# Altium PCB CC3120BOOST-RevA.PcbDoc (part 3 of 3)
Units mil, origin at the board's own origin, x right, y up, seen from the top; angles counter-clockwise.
Board outline 2300 x 1700 mil, 4 copper layers (Top Layer, Mid-Layer 1, Mid-Layer 2, Bottom Layer), stack 90 mil thick; 155 components, 108 nets, 432 pads, 292 vias.
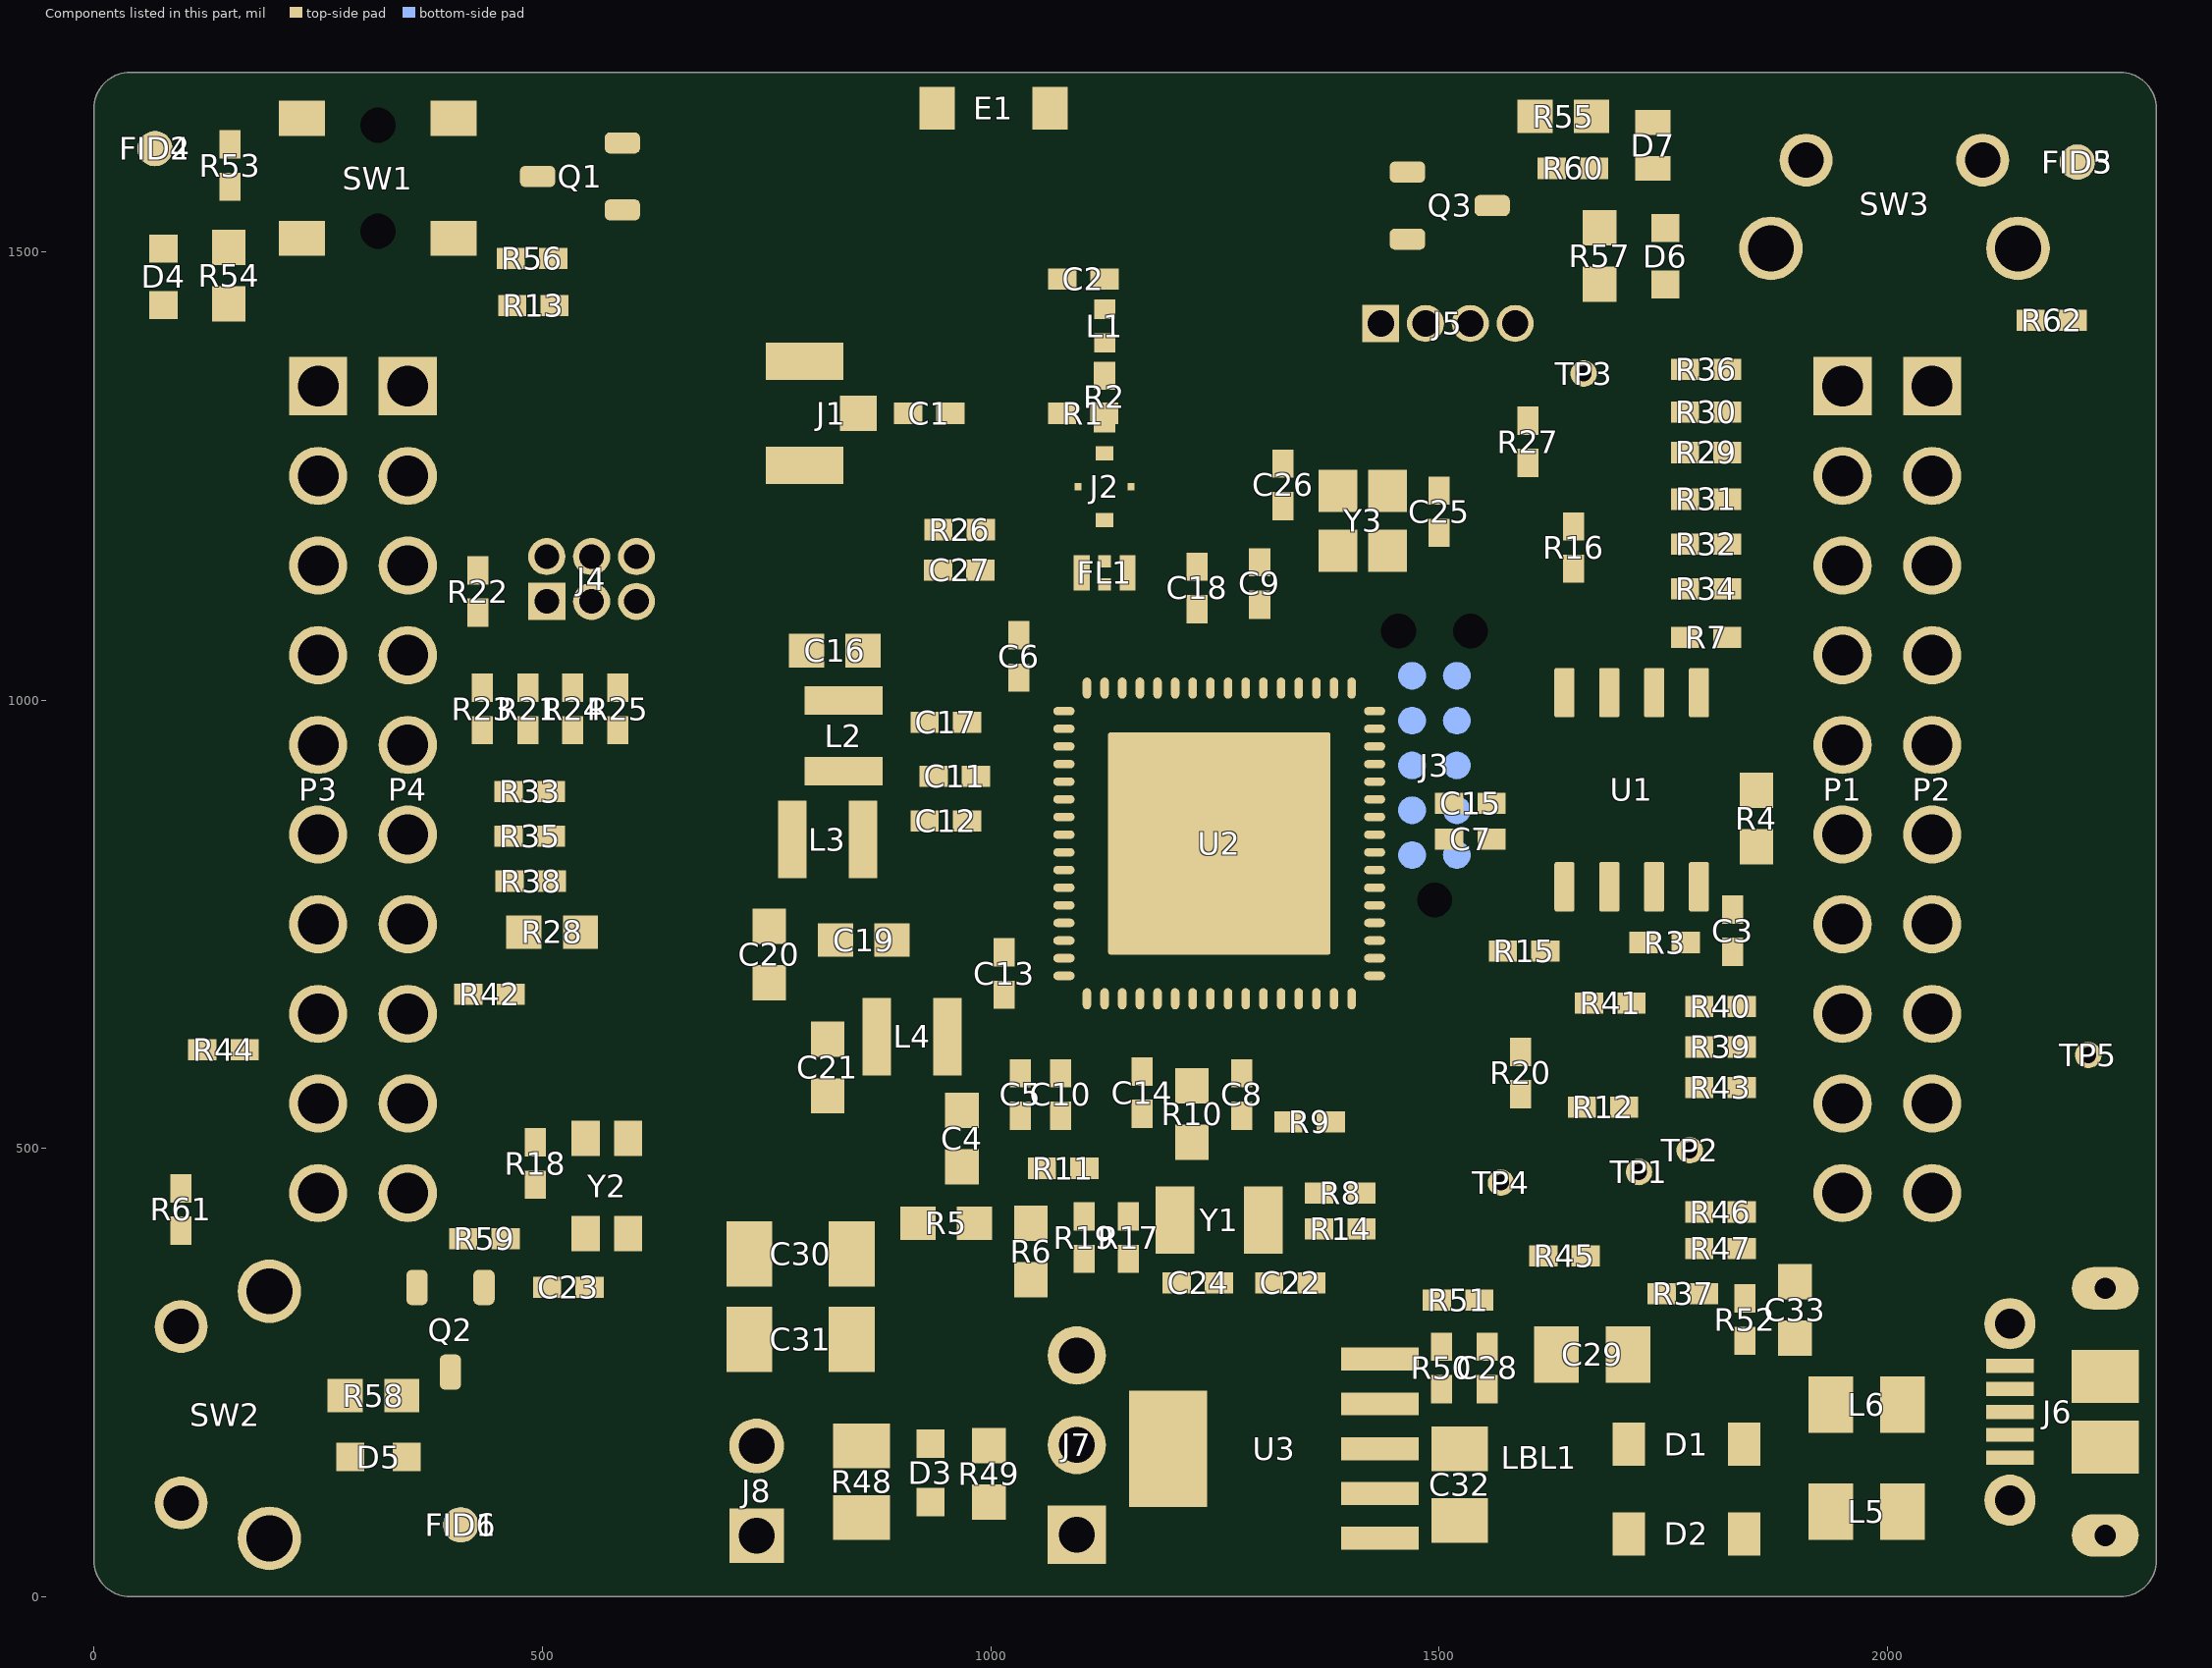
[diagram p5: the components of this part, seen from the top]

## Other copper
Top Layer:
  rectangle net GND: 1107,692 1402.28,987.28
  pour cut-out: 700,1210 716.9,1193.1 727.4,1193.1 724.5,1196 724.5,1220.6 704.3,1220.6 700,1216.3
  pour cut-out: 432.2,925 465.8,925 477.2,936.4 477.2,1000.4 467.5,1010.1 439.7,1010.1 418.1,988.5 418.1,936.4 429.3,925.2 432,925.2
  pour cut-out: 1519.7,259.4 1526.2,252.9 1535.7,252.9 1545.3,262.5 1545.3,291.5 1528.3,308.5 1524,304.2 1519.7,304.2
  pour cut-out: 744.8,460.7 772.9,488.8 909,488.8 915.2,482.6 918.5,482.6 932.5,496.6 932.5,515.6 877.2,570.9 720,570.9 701.4,552.3 701.4,480.5 723.3,458.6 726.4,461.7 745.5,461.7
  pour cut-out: 1005.6,1106.3 1005.6,1061.5 1018,1049.1 1049.1,1049.1 1055.5,1055.5 1055.5,1113.5 1042.2,1126.8 1024.3,1126.8 1004.7,1107.2
  pour cut-out: 753.7,453 661,453 643.33,470.67 643.33,764.33 658,779 658,892 658,1137 715,1194 707,1202 707,1227 713.4,1233.4 963.6,1233.4 967,1230 967,1136 962,1131 948.58,1131 935.4,1117.82 935.4,1038.6 968,1006 1037.8,936.2 1037.8,658.8 932,553 779,553 753.7,527.7
  pour cut-out: 888.04,1292.94 985.87,1292.94 985.87,1294.43 1048.79,1294.43 1048.79,1292.94 1100.19,1292.94 1100.19,1346.56 1048.79,1346.56 1048.79,1343.37 985.87,1343.37 985.87,1346.56 888.04,1346.56
  pour cut-out: 1100.19,1346.56 1100.19,1413.29 1104.7,1417.8 1153.8,1417.8 1153.8,1343.9 1149.5,1339.6 1107.15,1339.6
  region net GND: 1144.77,1225.37 1153.82,1216.31 1172.33,1216.31 1172.33,1259.62 1153.82,1259.62 1144.77,1250.57
  region net GND: 1109.33,1250.57 1100.28,1259.62 1081.77,1259.62 1081.77,1216.31 1100.28,1216.31 1109.33,1225.37
  pour cut-out: 1395.9,424.41 1384.15,436.16 1233.28,436.16 1173.12,376 1173.12,335.58 1175,333.7 1378.98,333.7 1395.9,350.62
  pour cut-out: 1214.24,300.33 1371.69,300.33 1379.68,308.32 1379.68,346.39 1367.46,358.61 1221.29,358.61 1212.36,349.68 1212.36,302.21
  pour cut-out: 1213,1128 1213,1202 1316,1305 1573,1305 1584,1316 1694,1316 1865,1145 1865,559 1767,461 1612,461 1535,538 1535,955 1379,1111 1229.34,1111 1215.22,1125.13
  pour cut-out: 1102,994 1102,694.84 1110.07,686.78 1397.92,686.78 1408.71,697.57 1408.71,984.44 1396.16,997 1105,997
  pour cut-out: 971.91,424.31 1516.43,424.31 1526.97,434.85 1526.97,558.16 1589.2,620.39 1589.2,737.06 1579.56,746.7 1546.58,746.7 1512.08,781.2 1445.73,781.2 1441.18,776.65 1441.18,675.81 1437.01,671.64 1437.01,629.17 1406.68,598.84 920.23,598.84 920.23,476.51 972.6,424.14
  pour cut-out: 1859,259 1857,261 1857,264 1862,269 1912,269 1915,266 1915,260 1914,259
  pour cut-out: 1158,1455 1138,1455 1137,1456 1137,1500 1142,1505 1156,1505 1158,1503
  pour cut-out: 1153.86,1424.2 1153.86,1405.9 1140.1,1405.9 1137,1409 1137,1496 1139,1498 1153,1498 1154,1497 1154,1424
  pour cut-out: 1117,1494.65 940.2,1494.65 940,1494.85 940,1636 961,1636 961,1692 1046,1692 1046,1636 1117,1636
  pour cut-out: 1490.33,1490.33 1439.33,1490.33 1439.33,1537.34 1490.33,1537.34 1490.33,1490.33
  pour cut-out: 287,1313 213,1313 213,1387 287,1387
  pour cut-out: 378.55,889 455.88,811.66 455.88,791 439.56,791 419.56,811 371.35,811 371.01,811.02 370.66,811.06 370.32,811.14 369.99,811.24 369.66,811.38 369.35,811.54 369.06,811.72 368.78,811.94 368.53,812.17 368.29,812.43 368.08,812.71 367.89,813 367.73,813.31 367.6,813.63 367.49,813.97 367.42,814.31 367.37,814.65 367.35,815 367.37,815.35 367.42,815.69 367.49,816.04 367.6,816.37 367.73,816.69 367.89,817 368.08,817.29 368.29,817.57 368.53,817.83 368.78,818.06 369.06,818.28 369.27,818.41 371.95,820.21 374.46,822.24 376.79,824.48 378.91,826.91 380.81,829.52 382.48,832.28 383.9,835.18 385.07,838.19 385.96,841.29 386.58,844.46 386.93,847.67 386.99,850.9 386.77,854.12 386.27,857.31 385.5,860.44 384.45,863.49 383.14,866.45 381.59,869.27 379.79,871.95 377.76,874.46 375.52,876.79 373.09,878.91 370.48,880.81 369.27,881.59 368.98,881.78 368.71,882 368.46,882.24 368.23,882.5 368.02,882.79 367.84,883.08 367.69,883.4 367.56,883.72 367.47,884.06 367.4,884.4 367.36,884.75 367.36,885.1 367.38,885.44 367.43,885.79 367.52,886.13 367.63,886.46 367.77,886.78 367.94,887.08 368.13,887.37 368.35,887.64 368.6,887.9 368.86,888.13 369.14,888.33 369.44,888.51 369.75,888.66 370.08,888.79 370.41,888.89 370.76,888.95 371.1,888.99 371.35,889 378.55,889
  pour cut-out: 1097,1005 1096,1004 1084,1004 1046,1042 1046,1073 1049,1070 1061,1070 1075,1056 1075,1078 1101,1078 1109,1070 1109,1039 1102,1032 1097,1032 1097,1005
  pour cut-out: 1040.99,1031.29 1040.99,1032.71 1054.97,1032.71 1059.83,1027.84 1059.83,1000.78 1058.7,1000.23 1057.67,999.67 1057.36,999.51 1057.04,999.37 1056.71,999.26 1056.37,999.18 1056.03,999.13 1055.68,999.11 1055.33,999.12 1054.98,999.16 1054.64,999.23 1054.31,999.33 1053.98,999.46 1053.67,999.62 1053.37,999.8 1053.09,1000.01 1052.83,1000.24 1052.59,1000.5 1052.38,1000.77 1052.19,1001.06 1052.02,1001.37 1051.88,1001.69 1051.86,1001.76 1051.2,1003.37 1050.4,1004.92 1049.47,1006.4 1048.41,1007.79 1047.24,1009.08 1045.96,1010.26 1044.58,1011.33 1043.11,1012.28 1041.57,1013.09 1039.96,1013.76 1038.3,1014.3 1036.6,1014.68 1034.87,1014.92 1033.12,1015 1031.38,1014.93 1029.65,1014.71 1027.94,1014.34 1027.31,1014.16 1026.97,1014.08 1026.62,1014.02 1026.28,1014 1025.93,1014 1025.58,1014.04 1025.24,1014.1 1024.9,1014.2 1024.58,1014.32 1024.26,1014.48 1023.96,1014.65 1023.68,1014.86 1023.41,1015.09 1023.17,1015.34 1022.95,1015.61 1022.76,1015.9 1022.59,1016.2 1022.44,1016.52 1022.33,1016.85 1022.24,1017.19 1022.19,1017.53 1022.18,1017.6 1021.9,1019.59 1021.44,1021.54 1020.82,1023.45 1020.03,1025.3 1019.92,1025.52 1019.78,1025.84 1019.67,1026.17 1019.58,1026.51 1019.53,1026.86 1019.51,1027.2 1019.51,1027.55 1019.55,1027.9 1019.62,1028.24 1019.72,1028.58 1019.84,1028.9 1020,1029.21 1020.18,1029.51 1020.39,1029.79 1020.62,1030.06 1020.87,1030.3 1021.14,1030.52 1021.43,1030.71 1021.74,1030.88 1022.06,1031.02 1022.39,1031.13 1022.72,1031.21 1023.07,1031.27 1023.42,1031.29 1023.51,1031.29 1040.99,1031.29
  pour cut-out: 1781.88,1087 1699.66,1087 1699.31,1087.02 1698.97,1087.06 1698.63,1087.14 1698.3,1087.24 1697.97,1087.38 1697.66,1087.54 1697.37,1087.72 1697.09,1087.94 1696.84,1088.17 1696.6,1088.43 1696.39,1088.71 1696.2,1089 1696.04,1089.31 1695.9,1089.63 1695.8,1089.96 1695.72,1090.31 1695.68,1090.65 1695.66,1091 1695.68,1091.35 1695.72,1091.69 1695.8,1092.04 1695.9,1092.37 1696.04,1092.69 1696.2,1093 1696.39,1093.29 1696.6,1093.57 1696.84,1093.83 1697.09,1094.06 1697.22,1094.17 1698.55,1095.29 1699.78,1096.53 1700.9,1097.87 1701,1098 1781.88,1098 1781.88,1087
  pour cut-out: 2197.55,96.93 2197.55,302.63 2204.97,310.05 2258.54,310.05 2267.53,301.06 2267.53,102.43 2252.67,87.57 2207.99,87.57 2197.52,98.04
  pour cut-out: 716,1236 687,1236 686,1235 686,1224 700,1210 714,1210 714,1229 716,1231
  pour cut-out: 1005,1172 1012,1179 1035,1179 1055,1159 1055,1070 1024,1070 1004,1090 1005,1091
  pour cut-out: 1158,1494.65 1132.23,1494.65 1126.8,1500.08 1117.03,1500.08 1117,1500.11
  pour cut-out: 1046.01,1636.01 1176.42,1636.01 1176.42,1494.65 1053.68,1494.65 1039.13,1509.2 1046,1516.07 1046,1636
  pour cut-out: 1117.01,1494.66 1117.01,1420.58 1119.04,1418.55 1137.67,1418.55 1141.56,1422.43 1141.56,1493.47 1137.49,1497.54 1119.88,1497.54
  pour cut-out: 808.47,115.38 820.81,127.71 912.74,127.71 912.74,105.13 902.65,95.04 828.01,95.04 808.15,114.9
  pour cut-out: 1580.7,1306.1 1669.6,1306.1 1684.2,1320.7 1684.2,1350.1 1657.4,1376.9 1610.5,1376.9 1574.8,1341.2 1574.8,1309.2 1578,1306 1580.7,1306
  pour cut-out: 744,496.6 764.5,496.6 773.2,505.3 773.2,541.6 752.8,562 752.8,566 695.1,566 688.9,559.8 688.9,507.4 699.6,496.7 745.8,496.7
  pour cut-out: 1101,1413 1101,1499 1104,1502 1113.92,1502 1117,1498.92 1117,1412 1116,1413
  text "L01 TOP LAYER" at 727,-858.49 h60
Mid-Layer 1:
  pour cut-out: 898.42,956.58 906.03,961.67 915,963.45 923.97,961.67 931.58,956.58 936.67,948.97 937.83,943.13 936.8,933.5 922.7,915.7 911.3,917.29 906.03,918.33 898.42,923.42 893.33,931.03 891.55,940 893.33,948.97
  pour cut-out: 880.12,827.82 875.03,835.43 873.25,844.4 875.03,853.37 880.12,860.98 887.73,866.07 893.57,867.23 903.2,866.2 921,852.1 919.41,840.7 918.37,835.43 913.28,827.82 905.67,822.73 896.7,820.95 887.73,822.73
  pour cut-out: 977.22,629.92 972.13,637.53 970.35,646.5 972.13,655.47 977.22,663.08 984.83,668.17 990.67,669.33 1000.3,668.3 1018.1,654.2 1016.51,642.8 1015.47,637.53 1010.38,629.92 1002.77,624.83 993.8,623.05 984.83,624.83
  pour cut-out: 995.95,1026.75 994.4,1034.55 989.98,1041.17 983.36,1045.59 975.56,1047.14 967.75,1045.59 961.14,1041.17 956.72,1034.55 955.16,1026.75 956.72,1018.95 961.14,1012.33 967.75,1007.91 975.56,1006.36 983.36,1007.91 989.98,1012.33 994.4,1018.95 995.95,1026.75
  pour cut-out: 841.91,27.75 873.58,27.75 885.2,39.37 885.2,62.42 878.74,68.88 838.82,68.88 835.54,65.6 835.54,34.02 841.8,27.77
  pour cut-out: 582.55,362.3 582.55,336.06 584.37,334.23 604.45,334.23 605.8,335.58 605.8,359.42 602.93,362.29 582.54,362.29
  pour cut-out: 505.4,1157.5 505.4,1107.5 605.4,1107.5 605.4,1157.5
  pour cut-out: 1530.39,480 1528.84,487.8 1524.42,494.42 1517.8,498.84 1510,500.39 1502.2,498.84 1495.58,494.42 1491.16,487.8 1489.61,480 1491.16,472.2 1495.58,465.58 1502.2,461.16 1510,459.61 1517.8,461.16 1524.42,465.58 1528.84,472.2 1530.39,480
  pour cut-out: 182 vertices and 0 holes, not listed, extent 1556.01,1115.01 1610.99,1194.99
  pour cut-out: 178 vertices and 0 holes, not listed, extent 1510.01,1215.01 1579.99,1284.99
  pour cut-out: 1285.39,1125 1283.84,1132.8 1279.42,1139.42 1272.8,1143.84 1265,1145.39 1257.2,1143.84 1250.58,1139.42 1246.16,1132.8 1244.61,1125 1246.16,1117.2 1250.58,1110.58 1257.2,1106.16 1265,1104.61 1272.8,1106.16 1279.42,1110.58 1283.84,1117.2 1285.39,1125
  pour cut-out: 1250.39,1288 1248.84,1295.8 1244.42,1302.42 1237.8,1306.84 1230,1308.39 1222.2,1306.84 1215.58,1302.42 1211.16,1295.8 1209.61,1288 1211.16,1280.2 1215.58,1273.58 1222.2,1269.16 1230,1267.61 1237.8,1269.16 1244.42,1273.58 1248.84,1280.2 1250.39,1288
  pour cut-out: 640.39,1010 638.84,1017.8 634.42,1024.42 627.8,1028.84 620,1030.39 612.2,1028.84 605.58,1024.42 601.16,1017.8 599.61,1010 601.16,1002.2 605.58,995.58 612.2,991.16 620,989.61 627.8,991.16 634.42,995.58 638.84,1002.2 640.39,1010
  pour cut-out: 625.65,903.44 624.1,911.24 619.68,917.85 613.06,922.28 605.26,923.83 597.46,922.28 590.84,917.85 586.42,911.24 584.87,903.44 586.42,895.63 590.84,889.02 597.46,884.6 605.26,883.04 613.06,884.6 619.68,889.02 624.1,895.63 625.65,903.44
  pour cut-out: 610.39,850 608.84,857.8 604.42,864.42 597.8,868.84 590,870.39 582.2,868.84 575.58,864.42 571.16,857.8 569.61,850 571.16,842.2 575.58,835.58 582.2,831.16 590,829.61 597.8,831.16 604.42,835.58 608.84,842.2 610.39,850
  pour cut-out: 614.99,319.7 613.44,327.5 609.02,334.12 602.4,338.54 594.6,340.09 586.8,338.54 580.18,334.12 575.76,327.5 574.21,319.7 575.76,311.9 580.18,305.28 586.8,300.86 594.6,299.31 602.4,300.86 609.02,305.28 613.44,311.9 614.99,319.7
  text "L02 GND LAYER" at 739,-834 h25
Mid-Layer 2:
  pour cut-out: 628.1,754.7 617.48,765.32 617.48,864.42 633.46,880.4 679.5,880.4 679.5,806.1
  pour cut-out: 526.59,337.8 525.04,345.6 520.62,352.22 514,356.64 506.2,358.19 498.4,356.64 491.78,352.22 487.36,345.6 485.81,337.8 487.36,330 491.78,323.38 498.4,318.96 506.2,317.41 514,318.96 520.62,323.38 525.04,330 526.59,337.8
  pour cut-out: 525.77,314.38 524.22,322.18 519.8,328.8 513.18,333.22 505.38,334.77 497.57,333.22 490.96,328.8 486.54,322.18 484.99,314.38 486.54,306.57 490.96,299.96 497.57,295.54 505.38,293.99 513.18,295.54 519.8,299.96 524.22,306.57 525.77,314.38
  pour cut-out: 644.4,657.4 644.4,520.1 652.6,511.9 711.7,511.9 715.2,515.4 715.2,586.6
  pour cut-out: 810.59,732.2 809.04,740 804.62,746.62 798,751.04 790.2,752.59 782.4,751.04 775.78,746.62 771.36,740 769.81,732.2 771.36,724.4 775.78,717.78 782.4,713.36 790.2,711.81 798,713.36 804.62,717.78 809.04,724.4 810.59,732.2
  pour cut-out: 798.59,560 797.04,567.8 792.62,574.42 786,578.84 778.2,580.39 770.4,578.84 763.78,574.42 759.36,567.8 757.81,560 759.36,552.2 763.78,545.58 770.4,541.16 778.2,539.61 786,541.16 792.62,545.58 797.04,552.2 798.59,560
  pour cut-out: 838.59,520 837.04,527.8 832.62,534.42 826,538.84 818.2,540.39 810.4,538.84 803.78,534.42 799.36,527.8 797.81,520 799.36,512.2 803.78,505.58 810.4,501.16 818.2,499.61 826,501.16 832.62,505.58 837.04,512.2 838.59,520
  pour cut-out: 1014.19,646.5 1012.64,654.3 1008.22,660.92 1001.6,665.34 993.8,666.89 986,665.34 979.38,660.92 974.96,654.3 973.41,646.5 974.96,638.7 979.38,632.08 986,627.66 993.8,626.11 1001.6,627.66 1008.22,632.08 1012.64,638.7 1014.19,646.5
  pour cut-out: 810.59,732.2 809.04,740 804.62,746.62 798,751.04 790.2,752.59 782.4,751.04 775.78,746.62 771.36,740 769.81,732.2 771.36,724.4 775.78,717.78 782.4,713.36 790.2,711.81 798,713.36 804.62,717.78 809.04,724.4 810.59,732.2
  pour cut-out: 1616.29,838.28 1614.74,846.08 1610.32,852.7 1603.7,857.12 1595.9,858.67 1588.1,857.12 1581.48,852.7 1577.06,846.08 1575.51,838.28 1577.06,830.48 1581.48,823.86 1588.1,819.44 1595.9,817.89 1603.7,819.44 1610.32,823.86 1614.74,830.48 1616.29,838.28
  pour cut-out: 1074.39,503.5 1072.84,511.3 1068.42,517.92 1061.8,522.34 1054,523.89 1046.2,522.34 1039.58,517.92 1035.16,511.3 1033.61,503.5 1035.16,495.7 1039.58,489.08 1046.2,484.66 1054,483.11 1061.8,484.66 1068.42,489.08 1072.84,495.7 1074.39,503.5
  pour cut-out: 1046.29,477.7 1044.74,485.5 1040.32,492.12 1033.7,496.54 1025.9,498.09 1018.1,496.54 1011.48,492.12 1007.06,485.5 1005.51,477.7 1007.06,469.9 1011.48,463.28 1018.1,458.86 1025.9,457.31 1033.7,458.86 1040.32,463.28 1044.74,469.9 1046.29,477.7
  pour cut-out: 1053.39,506 1051.84,513.8 1047.42,520.42 1040.8,524.84 1033,526.39 1025.2,524.84 1018.58,520.42 1014.16,513.8 1012.61,506 1014.16,498.2 1018.58,491.58 1025.2,487.16 1033,485.61 1040.8,487.16 1047.42,491.58 1051.84,498.2 1053.39,506
  pour cut-out: 1106.29,1145.3 1104.74,1153.1 1100.32,1159.72 1093.7,1164.14 1085.9,1165.69 1078.1,1164.14 1071.48,1159.72 1067.06,1153.1 1065.51,1145.3 1067.06,1137.5 1071.48,1130.88 1078.1,1126.46 1085.9,1124.91 1093.7,1126.46 1100.32,1130.88 1104.74,1137.5 1106.29,1145.3
  pour cut-out: 1107.39,1166 1105.84,1173.8 1101.42,1180.42 1094.8,1184.84 1087,1186.39 1079.2,1184.84 1072.58,1180.42 1068.16,1173.8 1066.61,1166 1068.16,1158.2 1072.58,1151.58 1079.2,1147.16 1087,1145.61 1094.8,1147.16 1101.42,1151.58 1105.84,1158.2 1107.39,1166
  pour cut-out: 1106.39,1121 1104.84,1128.8 1100.42,1135.42 1093.8,1139.84 1086,1141.39 1078.2,1139.84 1071.58,1135.42 1067.16,1128.8 1065.61,1121 1067.16,1113.2 1071.58,1106.58 1078.2,1102.16 1086,1100.61 1093.8,1102.16 1100.42,1106.58 1104.84,1113.2 1106.39,1121
  pour cut-out: 1106.39,1089.44 1104.84,1097.25 1100.42,1103.86 1093.8,1108.28 1086,1109.84 1078.2,1108.28 1071.58,1103.86 1067.16,1097.25 1065.61,1089.44 1067.16,1081.64 1071.58,1075.03 1078.2,1070.6 1086,1069.05 1093.8,1070.6 1100.42,1075.03 1104.84,1081.64 1106.39,1089.44
  pour cut-out: 1051.99,1105.7 1050.44,1113.5 1046.02,1120.12 1039.4,1124.54 1031.6,1126.09 1023.8,1124.54 1017.18,1120.12 1012.76,1113.5 1011.21,1105.7 1012.76,1097.9 1017.18,1091.28 1023.8,1086.86 1031.6,1085.31 1039.4,1086.86 1046.02,1091.28 1050.44,1097.9 1051.99,1105.7
  pour cut-out: 773.39,781.3 771.84,789.1 767.42,795.72 760.8,800.14 753,801.69 745.2,800.14 738.58,795.72 734.16,789.1 732.61,781.3 734.16,773.5 738.58,766.88 745.2,762.46 753,760.91 760.8,762.46 767.42,766.88 771.84,773.5 773.39,781.3
  pour cut-out: 739.99,747.9 738.44,755.7 734.02,762.32 727.4,766.74 719.6,768.29 711.79,766.74 705.18,762.32 700.76,755.7 699.2,747.9 700.76,740.09 705.18,733.48 711.79,729.06 719.6,727.5 727.4,729.06 734.02,733.48 738.44,740.09 739.99,747.9
  pour cut-out: 925.39,1000 923.84,1007.8 919.42,1014.42 912.8,1018.84 905,1020.39 897.2,1018.84 890.58,1014.42 886.16,1007.8 884.61,1000 886.16,992.2 890.58,985.58 897.2,981.16 905,979.61 912.8,981.16 919.42,985.58 923.84,992.2 925.39,1000
  pour cut-out: 703.64,741.8 779.5,817.66 779.5,1174.9 806.2,1201.6 869.9,1201.6 877.3,1209 877.3,1239.25 874.55,1242 668,1242 649.4,1223.4 649.4,1090.3 588,1028.9 588,920.7 605.26,903.44 605.26,876.64 628.1,853.8 628.1,754.7 641,741.8
  pour cut-out: 1199.79,508.4 1198.24,516.2 1193.82,522.82 1187.2,527.24 1179.4,528.79 1171.6,527.24 1164.98,522.82 1160.56,516.2 1159.01,508.4 1160.56,500.6 1164.98,493.98 1171.6,489.56 1179.4,488.01 1187.2,489.56 1193.82,493.98 1198.24,500.6 1199.79,508.4
  pour cut-out: 463.51,41 463.51,4.32 466.11,1.71 475.54,1.71 478.79,4.96 478.79,25.72
  pour cut-out: 919.4,66.86 919.4,56.71 925.91,50.2 939.78,50.2 945.06,55.48 945.06,69.3 938.57,75.8 925.62,75.8 919.35,69.52 919.35,66.7
  pour cut-out: 1900,61 1900,9 1896,5 1892,5 1869.98,27.02 1869.98,35.98 1895,61
  pour cut-out: 1155,1093 1151,1089 1151,1074 1156,1069 1172,1069 1180,1077 1180,1115 1173,1122 1160,1122 1155,1117
  pour cut-out: 1085.39,1243 1083.84,1250.8 1079.42,1257.42 1072.8,1261.84 1065,1263.39 1057.2,1261.84 1050.58,1257.42 1046.16,1250.8 1044.61,1243 1046.16,1235.2 1050.58,1228.58 1057.2,1224.16 1065,1222.61 1072.8,1224.16 1079.42,1228.58 1083.84,1235.2 1085.39,1243
  pour cut-out: 1301.39,180 1299.84,187.8 1295.42,194.42 1288.8,198.84 1281,200.39 1273.2,198.84 1266.58,194.42 1262.16,187.8 1260.61,180 1262.16,172.2 1266.58,165.58 1273.2,161.16 1281,159.61 1288.8,161.16 1295.42,165.58 1299.84,172.2 1301.39,180
  pour cut-out: 1301.39,120 1299.84,127.8 1295.42,134.42 1288.8,138.84 1281,140.39 1273.2,138.84 1266.58,134.42 1262.16,127.8 1260.61,120 1262.16,112.2 1266.58,105.58 1273.2,101.16 1281,99.61 1288.8,101.16 1295.42,105.58 1299.84,112.2 1301.39,120
  pour cut-out: 1301.39,65 1299.84,72.8 1295.42,79.42 1288.8,83.84 1281,85.39 1273.2,83.84 1266.58,79.42 1262.16,72.8 1260.61,65 1262.16,57.2 1266.58,50.58 1273.2,46.16 1281,44.61 1288.8,46.16 1295.42,50.58 1299.84,57.2 1301.39,65
  pour cut-out: 1244.39,65 1242.84,72.8 1238.42,79.42 1231.8,83.84 1224,85.39 1216.2,83.84 1209.58,79.42 1205.16,72.8 1203.61,65 1205.16,57.2 1209.58,50.58 1216.2,46.16 1224,44.61 1231.8,46.16 1238.42,50.58 1242.84,57.2 1244.39,65
  pour cut-out: 1196.39,65 1194.84,72.8 1190.42,79.42 1183.8,83.84 1176,85.39 1168.2,83.84 1161.58,79.42 1157.16,72.8 1155.61,65 1157.16,57.2 1161.58,50.58 1168.2,46.16 1176,44.61 1183.8,46.16 1190.42,50.58 1194.84,57.2 1196.39,65
  pour cut-out: 1075,223 1075.16,223.16 1116.26,223.16 1116.26,218.26 1107,209 1084,209 1075,218
  pour cut-out: 960.39,480 958.84,487.8 954.42,494.42 947.8,498.84 940,500.39 932.2,498.84 925.58,494.42 921.16,487.8 919.61,480 921.16,472.2 925.58,465.58 932.2,461.16 940,459.61 947.8,461.16 954.42,465.58 958.84,472.2 960.39,480
  pour cut-out: 182 vertices and 0 holes, not listed, extent 1556.01,1115.01 1610.99,1194.99
  pour cut-out: 178 vertices and 0 holes, not listed, extent 1510.01,1215.01 1579.99,1284.99
  pour cut-out: 1475.39,665 1473.84,672.8 1469.42,679.42 1462.8,683.84 1455,685.39 1447.2,683.84 1440.58,679.42 1436.16,672.8 1434.61,665 1436.16,657.2 1440.58,650.58 1447.2,646.16 1455,644.61 1462.8,646.16 1469.42,650.58 1473.84,657.2 1475.39,665
  pour cut-out: 625.65,903.44 624.1,911.24 619.68,917.85 613.06,922.28 605.26,923.83 597.46,922.28 590.84,917.85 586.42,911.24 584.87,903.44 586.42,895.63 590.84,889.02 597.46,884.6 605.26,883.04 613.06,884.6 619.68,889.02 624.1,895.63 625.65,903.44
  pour cut-out: 610.39,850 608.84,857.8 604.42,864.42 597.8,868.84 590,870.39 582.2,868.84 575.58,864.42 571.16,857.8 569.61,850 571.16,842.2 575.58,835.58 582.2,831.16 590,829.61 597.8,831.16 604.42,835.58 608.84,842.2 610.39,850
  pour cut-out: 935.39,940 933.84,947.8 929.42,954.42 922.8,958.84 915,960.39 907.2,958.84 900.58,954.42 896.16,947.8 894.61,940 896.16,932.2 900.58,925.58 907.2,921.16 915,919.61 922.8,921.16 929.42,925.58 933.84,932.2 935.39,940
  pour cut-out: 1188.39,1165 1186.84,1172.8 1182.42,1179.42 1175.8,1183.84 1168,1185.39 1160.2,1183.84 1153.58,1179.42 1149.16,1172.8 1147.61,1165 1149.16,1157.2 1153.58,1150.58 1160.2,1146.16 1168,1144.61 1175.8,1146.16 1182.42,1150.58 1186.84,1157.2 1188.39,1165
  pour cut-out: 1184.9,1166.91 1187.09,1169.09 1195.57,1169.09 1198.01,1171.52 1175.05,1194.48 1172.49,1194.48 1173.83,1193.13 1173.83,1178.12 1183.03,1168.93 1183.03,1167.54 1183.68,1166.9 1184.89,1166.9
  pour cut-out: 891.5,1140 900.71,1130.79 912.29,1130.79 920.5,1139 920.5,1150 911.5,1159 898.5,1159 891.5,1152
  pour cut-out: 1098.39,505.83 1096.84,513.63 1092.42,520.24 1085.8,524.66 1078,526.22 1070.2,524.66 1063.58,520.24 1059.16,513.63 1057.61,505.83 1059.16,498.02 1063.58,491.41 1070.2,486.99 1078,485.43 1085.8,486.99 1092.42,491.41 1096.84,498.02 1098.39,505.83
  pour cut-out: 1494.89,669.02 1493.34,676.83 1488.92,683.44 1482.3,687.86 1474.5,689.41 1466.7,687.86 1460.08,683.44 1455.66,676.83 1454.11,669.02 1455.66,661.22 1460.08,654.6 1466.7,650.18 1474.5,648.63 1482.3,650.18 1488.92,654.6 1493.34,661.22 1494.89,669.02
  pour cut-out: 1262.3,501.4 1262.3,471.2 1285.3,448.2 1371.5,448.2 1385.5,462.2 1385.5,502.7 1370.1,518.1 1272.1,518.1 1262.4,508.4 1262.4,500.4
  pour cut-out: 917.09,844.4 915.54,852.2 911.12,858.82 904.5,863.24 896.7,864.79 888.9,863.24 882.28,858.82 877.86,852.2 876.31,844.4 877.86,836.6 882.28,829.98 888.9,825.56 896.7,824.01 904.5,825.56 911.12,829.98 915.54,836.6 917.09,844.4
  text "L03 POWER LAYER" at 692,-834 h25
Bottom Layer:
  pour cut-out: 1378.22,320 1376.67,327.8 1372.25,334.42 1365.63,338.84 1357.83,340.39 1350.02,338.84 1343.41,334.42 1338.99,327.8 1337.43,320 1338.99,312.2 1343.41,305.58 1350.02,301.16 1357.83,299.61 1365.63,301.16 1372.25,305.58 1376.67,312.2 1378.22,320
  pour cut-out: 1275.05,320 1273.5,327.8 1269.08,334.42 1262.47,338.84 1254.66,340.39 1246.86,338.84 1240.24,334.42 1235.82,327.8 1234.27,320 1235.82,312.2 1240.24,305.58 1246.86,301.16 1254.66,299.61 1262.47,301.16 1269.08,305.58 1273.5,312.2 1275.05,320
  pour cut-out: 1014.19,646.5 1012.64,654.3 1008.22,660.92 1001.6,665.34 993.8,666.89 986,665.34 979.38,660.92 974.96,654.3 973.41,646.5 974.96,638.7 979.38,632.08 986,627.66 993.8,626.11 1001.6,627.66 1008.22,632.08 1012.64,638.7 1014.19,646.5
  pour cut-out: 838.59,520 837.04,527.8 832.62,534.42 826,538.84 818.2,540.39 810.4,538.84 803.78,534.42 799.36,527.8 797.81,520 799.36,512.2 803.78,505.58 810.4,501.16 818.2,499.61 826,501.16 832.62,505.58 837.04,512.2 838.59,520
  pour cut-out: 651,1224 651,1041 620,1010 620,959.3 626,953.3 626,537.1 694.6,468.5 749.3,468.5 764.9,484.1 764.9,526.1 772,526.1 796,550.1 796,567.8 828.5,600.3 828.5,917.4 882.4,971.3 1014.6,971.3 1024,980.7 1024,1085.4 1014.2,1095.2 1014.2,1210.3 984.8,1239.7 663.7,1239.7 650.9,1226.9 650.9,1224
  pour cut-out: 1530,1265 1592.5,1265 1598.3,1270.8 1598.3,1373.6 1551.6,1420.3 1490.8,1420.3 1481.8,1411.3 1481.8,1343.8 1530,1295.6
  pour cut-out: 1580,706 1580,741.5 1576.5,745 1566.3,745 1563.9,742.6 1563.9,710.9 1569.3,705.5 1569.8,706
  pour cut-out: 923.86,478 938,463.86 943.66,463.86 954.97,475.17 954.97,483.66 942.95,495.68 934.47,495.68 923.86,485.07
  pour cut-out: 1455,680 1499,680 1504,675 1504,661 1496,653 1466,653 1454,665 1455,666
  pour cut-out: 1580,725 1580,706 1596.13,689.87 1596.13,662.13 1565,631 1565,635 1547,653 1547,718 1559,730 1564,725
  pour cut-out: 1527,361 1531,357 1531,353 1537,347 1551,347 1564,360 1629,360 1633,364 1620,377 1515,377 1505,367 1505,363 1507,361
  pour cut-out: 1272,259 1279,252 1293,252 1299,258 1299,273 1294,278 1278,278 1272,272
  pour cut-out: 1212,259 1219,252 1233,252 1239,258 1239,273 1234,278 1218,278 1212,272
  pour cut-out: 1162,259 1169,252 1183,252 1189,258 1189,273 1184,278 1168,278 1162,272
  pour cut-out: 897,932 906,923 922,923 931,932 931,950 924,957 905,957 897,949
  pour cut-out: 1131.7,534.9 1131.7,463.2 1156.8,438.1 1378.7,438.1 1391,450.4 1391,542.9 1372.7,561.2 1158.1,561.2 1131.8,534.9
  pour cut-out: 917.09,844.4 915.54,852.2 911.12,858.82 904.5,863.24 896.7,864.79 888.9,863.24 882.28,858.82 877.86,852.2 876.31,844.4 877.86,836.6 882.28,829.98 888.9,825.56 896.7,824.01 904.5,825.56 911.12,829.98 915.54,836.6 917.09,844.4
  pour cut-out: 590,850 590,980 651,1041 651,831 645.5,825.5 612.5,825.5 584.4,853.6
  text "L04 BOTTOM LAYER" at 727,-858.49 h60

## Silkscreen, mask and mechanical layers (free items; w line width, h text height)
Top Overlay:
  drawing of 2705 lines, arcs and shapes, not listed
  text "FRST" at 88.2,1658.9 h30
  text "CC3120BOOST" at 677.5,1529.7 h50
  text "Rev A" at 679.7,1469.7 h40
  text "P4" at 1929,1417 h30
  text "P2" at 2025,1417 h30
  text "RST" at 1804.8,1414.9 h32
  text "P3" at 325.4,1409.7 h30
  text "P1" at 222.4,1408.6 h30
  text "RF" at 760,1401 h40
  text "IRQ" at 2121.4,1231.7 h30
  text "CS#" at 2115.1,1145.2 h30
  text "TX" at 130.4,1130.5 h30
  text "RX" at 130.1,1034.6 h30
  text "CTS" at 1826.1,1009.7 h30
  text "RTS" at 1828.9,938.1 h30
  text "RST" at 2122.9,933.5 h30
  text "nHIB" at 77.9,931.1 h30
  text "MOSI" at 2120.3,838 h30
  text "MISO" at 2086.7,735.7 h30
  text "CLK" at 98.3,735.1 h30
  text "NWP" at 1902,708 h30 r90
  text "FRST" at 77.1,640.3 h30
  text "MAC" at 1905,598 h30 r90
  text "RST*" at 2122.5,436.7 h30
  text "LDO" at 1158,258 h32
  text "PWR" at 947,201 h30 r90
  text "VBAT_CC" at 478.5,151.9 h32
  text "nHIB" at 250.3,87.6 h30
  text "VCC_BRD" at 473,52 h32
  text "MCU" at 1156,47 h32
  text "USB PWR" at 1930.68,13.61 h30
  text ".Layer_Name" at 727,-858.49 h60
Bottom Overlay:
  drawing of 3764 lines, arcs and shapes, not listed
  text "3V3" at 142.3,1332.6 h72.83
  text "GND" at 2275.3,1331.5 h72.83
  text "5V" at 551.3,1324.6 h72.83
  text "GND" at 586.3,1225.1 h72.83
  text "IRQ" at 2201.2,1191.3 h30
  text "TX" at 199.5,1099.5 h30
  text "CS#" at 2201,1095.3 h30
  text "CTS" at 1899.6,998.8 h30
  text "RX" at 199.8,998.5 h30
  text "nHIB" at 197.9,898.5 h30
  text "RST" at 2201.2,898 h30
  text "RTS" at 1900.5,896.8 h30
  text "MOSI" at 2201.1,798.8 h30
  text "CLK" at 198.4,699.1 h30
  text "MISO" at 2200.7,697.9 h30
  text "NWP" at 1899,691.3 h30
  text "FRST" at 199.1,599.3 h30
  text "MAC" at 1900.4,594.5 h30
  text "RST*" at 2200.7,397.5 h30
  text "not FCC approved for resale." at 1464.4,361.2 h60
  text "WCS001" at 1924.3,252.6 h50
  text ".Layer_Name" at 727,-858.49 h60
Top Paste:
  rectangle: 1146.18,1125 1159.18,1138
  rectangle: 1146.18,1146 1159.18,1159
  rectangle: 1095,1146 1108,1159
  rectangle: 1095,1125 1108,1138
  text ".Layer_Name" at 727,-858.49 h60
Bottom Paste:
  text ".Layer_Name" at 727,-858.49 h60
Top Solder:
  text ".Layer_Name" at 727,-858.49 h60
  text ".Layer_Name" at 727,-858.49 h60
Bottom Solder:
  text ".Layer_Name" at 727,-858.49 h60
Drill Guide:
  text ".Layer_Name" at 727,-858.49 h60
M1 Board Outline:
  the board outline again, w10
M2 Board Dimensions:
  rectangle: 275,-400 650,-275
  rectangle: 150,-275 275,-150
  lines w1: 2208.99,1759 2210,1760
  lines w7: 150,-275 1150,-275 ; 275,-400 275,-150 ; 400,-400 400,-150 ; 650,-400 650,-150 ; 900,-400 900,-150 ; 150,-400 150,-150 1150,-150 1150,-400 150,-400
  lines w10: -77.03,0.12 -0.85,0.12 ; -19.29,-18.32 -0.85,0.12 ; -19.29,18.57 -0.85,0.12 ; 2291.28,1726.64 2291.28,1691.28 ; 2326.64,1691.28 2291.28,1691.28 ; 2361.99,1762 2291.28,1691.28 ; 2363,1763 2548,1763
  text "R" at 2568,1753 h25
  text "40.00 mil X4" at 2608,1753 h25
  text "(0,0)" at -125.16,-57.16 h25
M3 3D STEP Top:
  text ".Layer_Name" at 727,-858.49 h60
M4 3D STEP Bottom:
  text ".Layer_Name" at 727,-858.49 h60
M5 Assembly Top:
  circle w6: c2088.18,154.32 r8
  circle w6: c1456.65,1113.48 r8
  circle w6: c1818.81,1026.37 r8
  circle w6: c668.69,24.35 r8
  circle w6: c1170.94,24.1 r8
  circle w6: c1434.88,31.28 r8
  circle w6: c1431,1489.4 r8
  circle w6: c1373.9,1415.5 r8
  circle w6: c626.8,1546.6 r8
  circle w6: c460.4,344.8 r8
  rectangle: 199.95,1413.88 217.3,1474.9
  rectangle: 1777.62,1664.6 1838.88,1676.98
  lines w10: -142,-930.17 6458,-930.17 ; -142,-726.83 6460,-726.83 ; -142,-523.5 -142,-1133.5 3863,-1133.5 6460,-1133.5 6460,-523.5 -141.5,-523.5 -141.5,-1133.5 1434,-1133.5 ; 2323,-1133.5 2323,-523.5 ; 3590,-726.83 3590,-523.5 ; 4430,-726.83 4430,-523.5 ; 5052,-1140 5052,-937.17
  text "COMPONENTS MARKED 'DNP' SHOULD NOT BE POPULATED." at 1303.5,-318.5 h60
  text "ASSEMBLY VARIANT:" at 1303,-434 h60
  text ".VariantName" at 2339,-434 h60
  text ".PRJ_Number" at 2863.59,-655.43 h60
  text "PCB VIEWED FROM TOP SIDE" at -78.5,-655.67 h60
  text "BOARD #:" at 2398,-655.67 h60
  text "REV:" at 3788,-655.67 h60
  text ".PCB_Rev" at 4079.5,-655.67 h60
  text "SVN REV:" at 4626,-655.67 h60
  text ".VersionControl_RevNumber" at 5132,-655.67 h60
  text ".Layer_Name" at 588,-866 h60
  text ".plot_File_Name" at 595.7,-1062.9 h60
  text "PLOT NAME =" at -78.5,-1064.33 h60
  text "GENERATED    :" at 2400,-1064.33 h60
  text ".Print_Date" at 3269.5,-1064.33 h60
  text ".Print_Time" at 3998.5,-1064.33 h60
  text "TEXAS INSTRUMENTS" at 5263,-1064.33 h60
M6 Assembly Bottom:
  lines w10: -142.5,-727.33 6459.5,-727.33 ; -140.5,-930.67 6459.5,-930.67 ; 1265.5,-1140.5 1265.5,-937.67 ; 1887.5,-727.33 1887.5,-524 ; 2727.5,-727.33 2727.5,-524 ; 3994.5,-1134 3994.5,-524 ; 4883.5,-1134 6459,-1134 6459,-524 -142.5,-524 -142.5,-1134 2454.5,-1134 6459.5,-1134 6459.5,-524
  text "COMPONENTS MARKED 'DNP' SHOULD NOT BE POPULATED." at 6252,-318 h60
  text ".VariantName" at 5208,-434 h60
  text "ASSEMBLY VARIANT:" at 6247,-434 h60
  text ".VersionControl_RevNumber" at 1185.5,-656.17 h60
  text "SVN REV:" at 1691.5,-656.17 h60
  text ".PCB_Rev" at 2238,-656.17 h60
  text "REV:" at 2529.5,-656.17 h60
  text ".PRJ_Number" at 3374,-656.17 h60
  text "BOARD #:" at 3919.5,-656.17 h60
  text "PCB VIEWED FROM BOTTOM SIDE" at 6396,-656.17 h60
  text ".Layer_Name" at 588,-866 h60
  text ".plot_File_Name" at 5736,-1059.7 h60
  text "TEXAS INSTRUMENTS" at 1054.5,-1064.83 h60
  text ".Print_Time" at 2319,-1064.83 h60
  text ".Print_Date" at 3048,-1064.83 h60
  text "GENERATED    :" at 3917.5,-1064.83 h60
  text "PLOT NAME =" at 6396,-1064.83 h60
M9 Title Sheet:
  drawing of 57 lines, arcs and shapes, not listed
  text "1" at 889.84,8036.5 h70
  text "2" at 3385.5,8036.5 h70
  text "3" at 5874.84,8036.5 h70
  text "4" at 8381.51,8036.5 h70
  text "5" at 10880.5,8036.5 h70
  text "6" at 13385.5,8036.5 h70
  text "A" at -266.5,6893.5 h70
  text "A" at 14533.5,6893.5 h70
  text "B" at -266.5,4513.5 h70
  text "B" at 14533.5,4513.5 h70
  text "C" at -266.5,2138.5 h70
  text "C" at 14533.5,2138.5 h70
  text "PROJECT TITLE:" at 11493.5,277.5 h45
  text ".PRJ_Title" at 11543.5,144.17 h70
  text "DESIGNED FOR:" at 11493.5,-23.5 h45
  text ".PRJ_Customer" at 11543.5,-163.5 h70
  text "D" at -266.5,-231.5 h70
  text "D" at 14533.5,-231.5 h70
  text "FILE NAME:" at 11493.5,-323.5 h45
  text ".PCB_File_Name_No_Path" at 11543.5,-443.5 h70
  text "Texas Instruments (TI) and/or its licensors do not warrant the accuracy or completeness of this specification" at 6524,-605.34 h45
  text "ENGINEER:" at 11493.5,-613.5 h45
  text "LAYOUT BY:" at 12998.5,-613.5 h45
  text "or any information contained therein. TI and/or its licensors do not warrant that this design will meet" at 6479.01,-718 h45
  text ".PRJ_Engineer" at 11543.5,-768.49 h70
  text ".PCB_Layout" at 13049,-768.49 h70
  text "the specifications, will be suitable for your application or fit for any particular purpose, or will operate in" at 6479.01,-830.67 h45
  text "ALTIUM DESIGNER VERSION:" at 12998.5,-923.5 h45
  text "an implementation. TI and/or its licensors do not warrant that the design is production worthy. You should" at 6479.01,-943.33 h45
  text "completely validate and test your design implementation to confirm the system functionality for your application." at 6524,-1056 h45
  text ".print_Scale" at 11543.5,-1056.83 h70
  text ".Application_BuildNumber" at 13049,-1056.83 h70
  text "1" at 889.84,-1263.5 h70
  text "2" at 3385.5,-1263.5 h70
  text "3" at 5874.84,-1263.5 h70
  text "4" at 8381.51,-1263.5 h70
  text "5" at 10880.5,-1263.5 h70
  text "6" at 13385.5,-1263.5 h70
M10 Fab Notes:
  drawing of 185 lines, arcs and shapes, not listed
  text "DESIGN INFORMATION" at 12531.02,5910 h60
  text "MIN. TRACK WIDTH:" at 11886.46,5730 h60
  text "6" at 12982.7,5730 h60
  text "MIL" at 13137.46,5730 h60
  text "6" at 12985,5600 h60
  text "MIN. CLEARANCE:" at 11886.46,5598 h60
  text "MIL" at 13137.46,5598 h60
  text "MIN. VIA PAD SIZE:" at 11886.46,5466 h60
  text "24" at 12952.71,5466 h60
  text "MIL" at 13137.46,5466 h60
  text "0.05mm (2MIL)" at 12581.46,5324.29 h60
  text "MINIMUM ANNULAR RING" at 11557.23,5320.01 h60
  text "EXTERNAL" at 13289.46,5320.01 h60
  text "PER" at 11757.23,5202 h60
  text "IPC-D-275 CLASS 2 LEVEL C" at 11977.23,5202 h60
  text "MIL, HOLES" at 13465.46,5089.71 h60
  text "+/-" at 13073,5089 h60
  text "+/-" at 13927,5089 h60
  text "REGISTRATION TOLERANCES:" at 11557.23,5084 h60
  text "METAL" at 12757,5084 h60
  text "5" at 13333.2,5084 h60
  text "3" at 14166.2,5084 h60
  text "MIL" at 14282.46,5084 h60
  text "MATERIAL:" at 11482.46,4874.54 h60
  text "FR-4 High Tg" at 12468.9,4734.21 h60
  text "FR-408" at 11903.46,4725.64 h60
  text "X" at 12315.46,4725.64 h60
  text "OTHER" at 13391.46,4725.64 h60
  text "1.2 mm+/-10%" at 13755,4565 h60
  text "62 MIL (1.6mm) +/-10%" at 12223.56,4562.92 h60
  text "THICKNESS:" at 11557.23,4558.64 h60
  text "X" at 13390.4,4558.64 h60
  text "OTHER" at 13488.46,4558.64 h60
  text "TOLERANCE:" at 11557.23,4400.64 h60
  text "X" at 12396.53,4400.64 h60
  text "ANSI IPC-6012 TYPE 3 CLASS 2" at 12583.48,4400.64 h60
  text "OTHER +/-" at 12583.46,4244.64 h60
  text "BOW & TWIST:" at 11557.23,4087.64 h60
  text "X" at 12396.53,4087.64 h60
  text "ANSI IPC-6012 TYPE 3 CLASS 2" at 12583.48,4087.64 h60
  text "OTHER +/-" at 12583.46,3929.13 h60
  text "DRILLING:" at 11482.46,3790.64 h60
  text "REFERENCE:" at 11557.23,3673.64 h60
  text "X" at 12205.46,3673.64 h60
  text "AS SHOWN" at 12392.46,3673.64 h60
  text "X" at 13106.46,3673.64 h60
  text "NC_DRILL FILES" at 13243.46,3673.64 h60
  text "PTH MIN COPPER THICKNESS:" at 11557.23,3515.64 h60
  text "X" at 12907.46,3515.64 h60
  text "1MIL" at 13044.46,3515.64 h60
  text "OTHER" at 13541.46,3515.64 h60
  text "BOARD FINISH:" at 11482.46,3356.64 h60
  text "SILKSCREEN:" at 11637.68,3238.64 h60
  text "X" at 12586.46,3238.64 h60
  text "TOP" at 12712.46,3238.64 h60
  text "X" at 13096.46,3238.64 h60
  text "BOTTOM" at 13223.46,3238.64 h60
  text "SILKSCREEN COLOR:" at 11637.68,3071.64 h60
  text "X" at 12585.42,3071.64 h60
  text "WHITE" at 12712.46,3071.64 h60
  text "OTHER" at 13223.46,3071.64 h60
  text "SOLDER RESIST COLOR:" at 11637.68,2901.64 h60
  text "X" at 13310.42,2747.44 h60
  text "GREEN" at 12332.46,2742.44 h60
  text "BLUE" at 12923.46,2742.44 h60
  text "OTHER" at 13461.46,2742.44 h60
  text "RED" at 13851.46,2737.44 h60
  text "IMMERSION GOLD (ENIG)" at 12543.46,2553.92 h60
  text "ENEPIG" at 13881,2550.64 h60
  text "SURFACE FINISH:" at 11482.46,2549.64 h60
  text "X" at 12356.51,2549.64 h60
  text "IMM. TIN/SILVER OR EQUIV" at 11812,2392.64 h60
  text "OTHER" at 13243.46,2392.64 h60
  text "ARRAY/PANEL:" at 11482.46,2213.64 h60
  text "CUT AND TRIM PER MECH LAYER 1" at 12543.46,2209.35 h60
  text "N.C. ROUTE" at 12543.46,2057.64 h60
  text "X" at 13222.46,2057.64 h60
  text "V. SCORE" at 13409.46,2057.64 h60
  text "CERTIFICATION:" at 11482.46,1920.64 h60
  text "MATERIALS AND WORKMANSHIP FOR ALL PCBS" at 12207.46,1920.64 h60
  text "TO MEET OR EXCEED THE REQUIREMENTS OF:" at 12207.46,1822.64 h60
  text "X" at 11833.96,1686.14 h60
  text "ANSI IPC-A-600F CLASS ->" at 11972.96,1686.14 h60
  text "X" at 13612.02,1686.14 h60
  text "2" at 13730.96,1686.14 h60
  text "1" at 13415.96,1684.64 h60
  text "3" at 14084.96,1684.64 h60
  text "X" at 11836.02,1526.64 h60
  text "UL 94V-0" at 11972.96,1526.64 h60
  text "X" at 12648.02,1526.64 h60
  text "RoHS" at 12784.96,1526.64 h60
  text "OTHER" at 13429.36,1526.64 h60
  text "PER ORDER" at 13826.42,1526.64 h60
  text "ADDITIONAL REQUIREMENTS:" at 11482.46,1385.64 h60
  text "MICROSECTION:" at 11557.23,1270.64 h60
  text "YES" at 12462.96,1270.64 h60
  text "REQUIRED" at 13324.46,1114.5 h60
  text "BARE BOARD ELEC. TEST:" at 11557.23,1111.64 h60
  text "NONE" at 12862.96,1111.64 h60
  text "X" at 13197.46,1111.64 h60
  text "PER ORDER" at 13916.46,1111.64 h60
  text "MANUFACTURER'S UL:" at 11557.23,954.64 h60
  text "RAIL" at 12722.96,950.35 h60
  text "METAL" at 13214.77,950.35 h60
  text "X" at 13590,950 h60
  text "SILK" at 13726.46,950.35 h60
M11 Gerber Information:
  lines w10: -142,-930.17 6458,-930.17 ; -142,-726.83 6460,-726.83 ; -142,-523.5 -142,-1133.5 3863,-1133.5 6460,-1133.5 6460,-523.5 -141.5,-523.5 -141.5,-1133.5 1434,-1133.5 ; 2323,-1133.5 2323,-523.5 ; 3590,-726.83 3590,-523.5 ; 4430,-726.83 4430,-523.5 ; 5052,-1140 5052,-937.17
  text "ALL ARTWORK VIEWED FROM TOP SIDE" at -78.5,-655.67 h60
  text "BOARD #:" at 2398,-655.67 h60
  text ".PRJ_Number" at 2943.5,-655.67 h60
  text "REV:" at 3788,-655.67 h60
  text ".PCB_Rev" at 4079.5,-655.67 h60
  text "SVN REV:" at 4626,-655.67 h60
  text ".VersionControl_RevNumber" at 5132,-655.67 h60
  text "LAYER NAME =" at -78.5,-858.49 h60
  text ".plot_File_Name" at 610,-1050 h60
  text "PLOT NAME =" at -78.5,-1064.33 h60
  text "GENERATED    :" at 2400,-1064.33 h60
  text ".Print_Date" at 3269.5,-1064.33 h60
  text ".Print_Time" at 3998.5,-1064.33 h60
  text "TEXAS INSTRUMENTS" at 5263,-1064.33 h60
M12 Stackup:
  lines w1: 5173,4059 5203,4209 5143,4209 5173,4056.99 ; 5173,4729 5173,4056.99 ; 5173,5049 5173,5676.99 ; 6228.02,4056.99 5173,4056.99 ; 6243.02,5676.99 5173,5676.99 ; 5173,5676.99 5143,5539 5203,5539 5173,5676.99
  lines w6: 915,6139 1435,6139 1435,6219 915,6219 ; 1047,6862 10922,6862 ; 1675,5979 1675,5899 ; 1675,6059 1675,6139 ; 1755,6299 1635,6299 ; 1875,6299 1915,6299 1995,6299 ; 2115,6099 2195,6099 ; 2275,6567 2275,7162 ; 2595,6139 2195,6139 2195,6219 2595,6219 ; 4380,6562 4380,7162 ; 6435,6567 6435,7162 ; 8680,6567 8680,7162 ; 10922,6567 1047,6567 1047,7162 10925,7162 10925,6567 ; 1635,6299 1675,6339 1675,6259 1635,6299 ; 1675,5899 1715,5939 1635,5939 1675,5899 ; 1675,6139 1635,6099 1715,6099 1675,6139 ; 1995,6099 2075,6099 1995,6099 ; 1995,6099 2035,6139 2035,6059 1995,6099 ; 1995,6299 1955,6339 1955,6259 1995,6299 ; 2195,6099 2155,6139 2155,6059 2195,6099 ; 915,5819 2595,5819 2595,5899 915,5899 915,5819 ; 1635,6139 1635,6219 1995,6219 1995,6139 1635,6139
  lines w10: 6303.02,3856.99 6378.02,3856.99 ; 6343.02,5851.99 6418.02,5851.99 ; 6428.02,3856.99 6503.02,3856.99 ; 6468.02,5851.99 6543.02,5851.99 ; 6553.02,3856.99 6628.02,3856.99 ; 6593.02,5851.99 6668.02,5851.99 ; 6678.02,3856.99 6753.02,3856.99 ; 6718.02,5851.99 6793.02,5851.99 ; 6803.02,3856.99 6878.02,3856.99 ; 6843.02,5851.99 6918.02,5851.99 ; 6953.02,3856.99 7028.02,3856.99 ; 6968.02,5851.99 7043.02,5851.99 ; 7078.02,3856.99 7153.02,3856.99 ; 7093.02,5851.99 7168.02,5851.99 ; 7203.02,3856.99 7278.02,3856.99 ; 7218.02,5851.99 7293.02,5851.99 ; 7328.02,3856.99 7403.02,3856.99 ; 7343.02,5851.99 7418.02,5851.99 ; 7453.02,3856.99 7528.02,3856.99 ; 7468.02,5851.99 7543.02,5851.99 ; 7578.02,3856.99 7653.02,3856.99 ; 7593.02,5851.99 7668.02,5851.99 ; 7703.02,3856.99 7778.02,3856.99 ; 7718.02,5851.99 7793.02,5851.99 ; 6328.02,4056.99 7778.02,4056.99 7778.02,4106.99 6328.02,4106.99 6328.02,4056.99 ; 6328.02,4256.99 7778.02,4256.99 7778.02,4306.99 6328.02,4306.99 6328.02,4256.99 ; 6328.02,4406.99 7778.02,4406.99 7778.02,4556.99 6328.02,4556.99 6328.02,4406.99 ; 6328.02,4656.99 7778.02,4656.99 7778.02,4706.99 6328.02,4706.99 6328.02,4656.99 ; 6343.02,4776.99 7793.02,4776.99 7793.02,4926.99 6343.02,4926.99 6343.02,4776.99 ; 6343.02,5026.99 7793.02,5026.99 7793.02,5076.99 6343.02,5076.99 6343.02,5026.99 ; 6343.02,5176.99 7793.02,5176.99 7793.02,5326.99 6343.02,5326.99 6343.02,5176.99 ; 6343.02,5426.99 7793.02,5426.99 7793.02,5476.99 6343.02,5476.99 6343.02,5426.99 ; 6343.02,5626.99 7793.02,5626.99 7793.02,5676.99 6343.02,5676.99 6343.02,5626.99
  text "CONTROLLED IMPEDANCE USING CPW with GND" at 3683.5,7315.33 h70
  text "GAP" at 5205,6968.67 h70
  text "REFERENCE GND" at 9045,6958.67 h70
  text "IMPEDANCE +/- 10%" at 6538.5,6945.33 h70
  text "LAYER NO" at 1149.5,6940.33 h70
  text "CONDUCTOR WIDTH" at 2441.5,6935.33 h70
  text "L2" at 9485,6668.67 h70
  text "15 mil" at 5055.5,6660.33 h70
  text "50 OHMS" at 7288.5,6660.33 h70
  text "18.0 MIL" at 3043.5,6650.33 h70
  text "1" at 1175.5,6645.33 h70
  text "W" at 1775,6275.67 h70
  text "L1" at 2670,6145.67 h70
  text "4-LAYER STACK BUILD" at 5840.98,6029.67 h80
  text "G" at 2055,6005.67 h70
  text "H" at 1630,5980.67 h70
  text "L2" at 2665,5840.67 h70
  text "PRIMARY SIDE, SILK SCREEN" at 7903.02,5791.99 h80
  text "SOLDER MASK(RED)------------->0.025 mm" at 7903.02,5596.99 h80
  text "LAYER 01 TOP LAYER   ----->0.035 mm" at 7903.02,5396.99 h80
  text "DIELECTRIC              ----->0.255 mm" at 7895.95,5216.72 h80
  text "LAYER 02  GND LAYER  ----->0.035 mm" at 7908.02,5001.99 h80
  text "1.2 mm+/-10%" at 4740,4830 h80
  text "DIELECTRIC              ----->0.5   mm" at 7911.55,4820.01 h80
  text "LAYER 03 POWER LAYER ----->0.035 mm" at 7893.02,4631.99 h80
  text "DIELECTRIC              ----->0.255 mm" at 7893.02,4431.99 h80
  text "LAYER 04 BOTTOM LAYER ----->0.035 mm" at 7898.02,4231.99 h80
  text "SOLDER MASK(RED)------------->0.025 mm" at 7883.02,4026.99 h80
  text "SECONDARY SIDE, SILK SCREEN" at 7883.02,3801.99 h80
  text "THIS IS AN IMPEDANCE CONTROLLED BOARD" at 5689,3653.3 h80
M13 Component Bodies Top:
  lines w6: 150,0 150,350 2150,350
  text ".Layer_Name" at 727,-858.49 h60
M14 Component Bodies Bottom:
  text ".Layer_Name" at 727,-858.49 h60
M15 Courtyards Top:
  text ".Layer_Name" at 727,-858.49 h60
M16 Courtyards Bottom:
  text ".Layer_Name" at 727,-858.49 h60
Drill Drawing:
  lines w15: 4429.3,797.3 11397.39,797.3 ; 4429.3,3197.3 11397.39,3197.3 ; 4980.18,647.3 4980.18,3347.3 ; 5677.99,647.3 5677.99,3347.3 ; 7023.59,647.3 7023.59,3347.3 ; 7529.47,647.3 7529.47,3347.3 ; 8263.27,647.3 8263.27,3347.3 ; 9404.94,647.3 9404.94,3347.3 ; 10618.59,647.3 10618.59,3347.3 ; 4429.3,647.3 11397.39,647.3 11397.39,3347.3 4429.3,3347.3 4429.3,647.3
  text "ADDITIONAL FAB NOTES" at -36,4895.4 h100
  text "1.12MIL &16 MIL VIAS ARE TENTED ON BOTH SIDES." at -36,4701.9 h100
  text "2.ALL OTHER DRILL TOLERANCE FOR PLATED +/-3 MIL AND NPTH +/-2 MIL" at -36,4492.8 h100
  text "(UNLESS OTHERWISE SPECIFIED)" at -28.2,4268.4 h100
  text "Symbol" at 4519.3,3242.3 h72
  text "Hit Count" at 5025.18,3242.3 h72
  text "Finished Hole Size" at 5722.99,3242.3 h72
  text "Plated" at 7068.59,3242.3 h72
  text "Hole Type" at 7574.47,3242.3 h72
  text "Physical Length" at 8308.27,3242.3 h72
  text "Rout Path Length" at 9449.94,3242.3 h72
  text "Tolerance" at 10663.59,3242.3 h72
  text "224" at 5025.18,3092.3 h60
  text "12.00mil (0.305mm)" at 5722.99,3092.3 h60
  text "PTH" at 7068.59,3092.3 h60
  text "Round" at 7574.47,3092.3 h60
  text "-" at 8308.27,3092.3 h60
  text "-" at 9449.94,3092.3 h60
  text "O" at 4490.21,3082.31 h66.67
  text "36" at 5025.18,2942.3 h60
  text "12.10mil (0.307mm)" at 5722.99,2942.3 h60
  text "PTH" at 7068.59,2942.3 h60
  text "Round" at 7574.47,2942.3 h60
  text "-" at 8308.27,2942.3 h60
  text "-" at 9449.94,2942.3 h60
  text "N" at 4490.21,2932.31 h66.67
  text "23" at 5025.18,2792.3 h60
  text "16.00mil (0.406mm)" at 5722.99,2792.3 h60
  text "PTH" at 7068.59,2792.3 h60
  text "Round" at 7574.47,2792.3 h60
  text "-" at 8308.27,2792.3 h60
  text "-" at 9449.94,2792.3 h60
  text "Q" at 4490.21,2782.31 h66.67
  text "5" at 5025.18,2642.3 h60
  text "17.72mil (0.450mm)" at 5722.99,2642.3 h60
  text "PTH" at 7068.59,2642.3 h60
  text "Round" at 7574.47,2642.3 h60
  text "-" at 8308.27,2642.3 h60
  text "-" at 9449.94,2642.3 h60
  text "C" at 4490.21,2632.31 h66.67
  text "9" at 5025.18,2492.3 h60
  text "20.00mil (0.508mm)" at 5722.99,2492.3 h60
  text "PTH" at 7068.59,2492.3 h60
  text "Round" at 7574.47,2492.3 h60
  text "-" at 8308.27,2492.3 h60
  text "-" at 9449.94,2492.3 h60
  text "P" at 4490.21,2482.31 h66.67
  text "2" at 5025.18,2342.3 h60
  text "23.62mil (0.600mm)" at 5722.99,2342.3 h60
  text "PTH" at 7068.59,2342.3 h60
  text "Slot" at 7574.47,2342.3 h60
  text "51.18mil (1.300mm)" at 8308.27,2342.3 h60
  text "27.56mil (0.700mm)" at 9449.94,2342.3 h60
  text "L" at 4490.21,2332.31 h66.67
  text "6" at 5025.18,2192.3 h60
  text "27.56mil (0.700mm)" at 5722.99,2192.3 h60
  text "PTH" at 7068.59,2192.3 h60
  text "Round" at 7574.47,2192.3 h60
  text "-" at 8308.27,2192.3 h60
  text "-" at 9449.94,2192.3 h60
  text "I" at 4501.32,2182.31 h66.67
  text "4" at 5025.18,2042.3 h60
  text "29.53mil (0.750mm)" at 5722.99,2042.3 h60
  text "PTH" at 7068.59,2042.3 h60
  text "Round" at 7574.47,2042.3 h60
  text "-" at 8308.27,2042.3 h60
  text "-" at 9449.94,2042.3 h60
  text "H" at 4490.21,2032.31 h66.67
  text "2" at 5025.18,1892.3 h60
  text "33.46mil (0.850mm)" at 5722.99,1892.3 h60
  text "PTH" at 7068.59,1892.3 h60
  text "Round" at 7574.47,1892.3 h60
  text "-" at 8308.27,1892.3 h60
  text "-" at 9449.94,1892.3 h60
  text "M" at 4490.21,1882.31 h66.67
  text "3" at 5025.18,1742.3 h60
  text "39.00mil (0.991mm)" at 5722.99,1742.3 h60
  text "NPTH" at 7068.59,1742.3 h60
  text "Round" at 7574.47,1742.3 h60
  text "-" at 8308.27,1742.3 h60
  text "-" at 9449.94,1742.3 h60
  text "D" at 4490.21,1732.31 h66.67
  text "2" at 5025.18,1592.3 h60
  text "39.37mil (1.000mm)" at 5722.99,1592.3 h60
  text "NPTH" at 7068.59,1592.3 h60
  text "Round" at 7574.47,1592.3 h60
  text "-" at 8308.27,1592.3 h60
  text "-" at 9449.94,1592.3 h60
  text "G" at 4490.21,1582.31 h66.67
  text "4" at 5025.18,1442.3 h60
  text "39.37mil (1.000mm)" at 5722.99,1442.3 h60
  text "PTH" at 7068.59,1442.3 h60
  text "Round" at 7574.47,1442.3 h60
  text "-" at 8308.27,1442.3 h60
  text "-" at 9449.94,1442.3 h60
  text "E" at 4490.21,1432.31 h66.67
  text "3" at 5025.18,1292.3 h60
  text "40.00mil (1.016mm)" at 5722.99,1292.3 h60
  text "PTH" at 7068.59,1292.3 h60
  text "Round" at 7574.47,1292.3 h60
  text "-" at 8308.27,1292.3 h60
  text "-" at 9449.94,1292.3 h60
  text "A" at 4490.21,1282.31 h66.67
  text "2" at 5025.18,1142.3 h60
  text "40.16mil (1.020mm)" at 5722.99,1142.3 h60
  text "PTH" at 7068.59,1142.3 h60
  text "Round" at 7574.47,1142.3 h60
  text "-" at 8308.27,1142.3 h60
  text "-" at 9449.94,1142.3 h60
  text "J" at 4490.21,1132.31 h66.67
  text "40" at 5025.18,992.3 h60
  text "45.28mil (1.150mm)" at 5722.99,992.3 h60
  text "PTH" at 7068.59,992.3 h60
  text "Round" at 7574.47,992.3 h60
  text "-" at 8308.27,992.3 h60
  text "-" at 9449.94,992.3 h60
  text "K" at 4490.21,982.31 h66.67
  text "4" at 5025.18,842.3 h60
  text "51.18mil (1.300mm)" at 5722.99,842.3 h60
  text "PTH" at 7068.59,842.3 h60
  text "Round" at 7574.47,842.3 h60
  text "-" at 8308.27,842.3 h60
  text "-" at 9449.94,842.3 h60
  text "F" at 4490.21,832.31 h66.67
  text "369 Total" at 5025.18,692.3 h60
  text "Slot definitions :" at 4519.3,547.33 h60
  text "Rout Path Length" at 5551.99,547.33 h60
  text "= Calculated from tool start centre position to tool end centre position." at 6534.7,547.33 h60
  text "Physical Length" at 5551.99,447.35 h60
  text "= Rout Path Length + Tool Size = Slot length as defined in the PCB layout" at 6474.71,447.35 h60
  text "FAB" at 727,-858.49 h60
Mechanical 18:
  lines w3.94: 653.6,525.7 653.6,1224 666.7,1237.1 983.6,1237.1 1013.7,1207 1013.7,621.5 906.9,514.7 664.6,514.7 653.6,525.7
Mechanical 32:
  lines w1: 125,0 175,0 ; 150,-25 150,25

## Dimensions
2260,0 to 2260,1700 on M2 Board Dimensions
0,40 to 2300,40 on M2 Board Dimensions
150,-400 to 1150,-400 on M2 Board Dimensions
